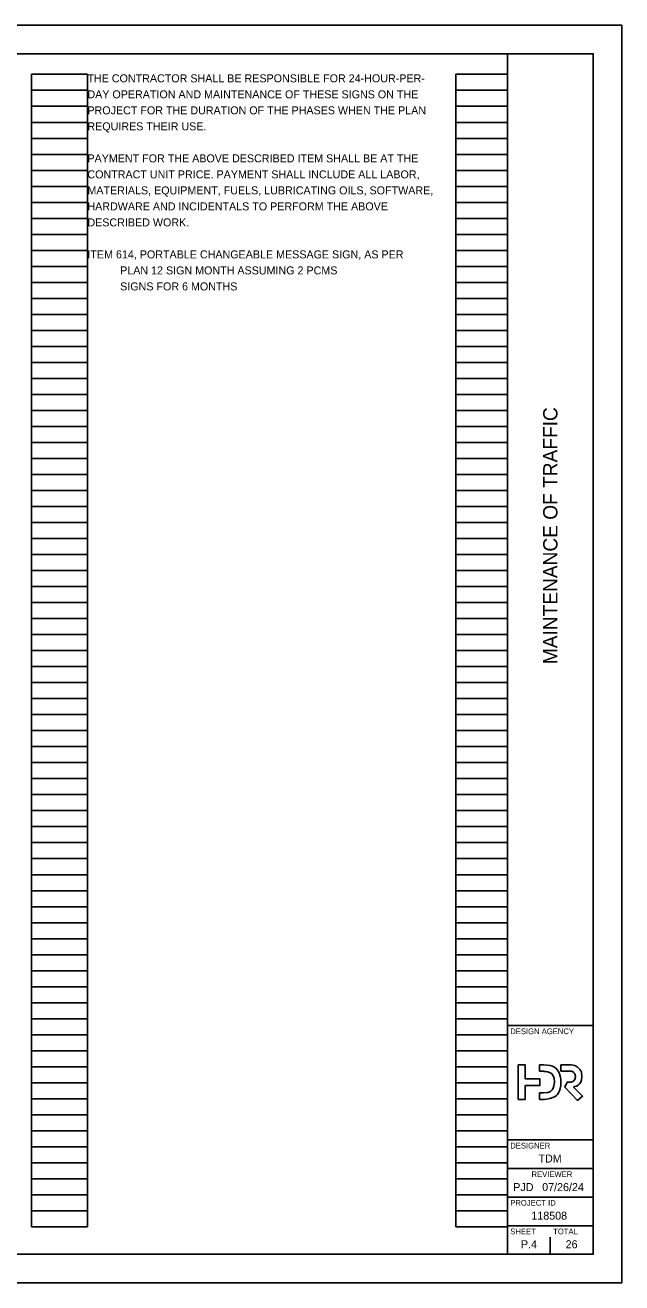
# Model space of a CAD drawing. Extents: x -9 to 65.1, y -15.6 to 23.2.
# Drawn here: x 23.57 to 34, y 0 to 22 of the extents above; entities that cross this region are included whole.
import ezdxf

# ---------------------------------------------------------------- set-up
doc = ezdxf.new("R2010")
doc.units = 0
for name, color, linetype in [('SH_Border', 7, 'Continuous'), ('SH_Cut_Line', 7, 'Continuous'), ('SH_Data', 7, 'Continuous'), ('SH_Text', 7, 'Continuous')]:
    doc.layers.add(name, color=color, linetype=linetype)

msp = doc.modelspace()

# ---------------------------------------------------------------- linework, layer by layer
at = {"layer": 'SH_Border'}
for p, q in [((32, 0.5), (32, 21.5)), ((32, 4.5), (33.5, 4.5)), ((32, 2.5), (33.5, 2.5)), ((32, 2), (33.5, 2)), ((32, 1.5), (33.5, 1.5)), ((32, 1), (33.5, 1))]:
    msp.add_line(p, q, dxfattribs=at)
msp.add_lwpolyline([(1.5, 21.5), (33.5, 21.5), (33.5, 0.5), (1.5, 0.5)], close=True, dxfattribs=at)
at = {"layer": 'SH_Cut_Line'}
msp.add_lwpolyline([(0, 0), (34, 0), (34, 22), (0, 22)], close=True, dxfattribs=at)
at = {"layer": 'SH_Data'}
for p, q in [((23.68, 0.98), (23.68, 21.14)), ((23.68, 21.14), (24.66, 21.14)), ((24.66, 0.98), (24.66, 21.14)), ((31.1, 0.98), (31.1, 21.14)), ((31.1, 21.14), (32, 21.14)), ((32, 0.98), (32, 21.14)), ((23.68, 20.86), (24.66, 20.86)), ((31.1, 20.86), (32, 20.86)), ((23.68, 20.58), (24.66, 20.58)), ((31.1, 20.58), (32, 20.58)), ((23.68, 20.3), (24.66, 20.3)), ((31.1, 20.3), (32, 20.3)), ((23.68, 20.02), (24.66, 20.02)), ((31.1, 20.02), (32, 20.02)), ((23.68, 19.74), (24.66, 19.74)), ((31.1, 19.74), (32, 19.74)), ((23.68, 19.46), (24.66, 19.46)), ((31.1, 19.46), (32, 19.46)), ((23.68, 19.18), (24.66, 19.18)), ((31.1, 19.18), (32, 19.18)), ((23.68, 18.9), (24.66, 18.9)), ((31.1, 18.9), (32, 18.9)), ((23.68, 18.62), (24.66, 18.62)), ((31.1, 18.62), (32, 18.62)), ((23.68, 18.34), (24.66, 18.34)), ((31.1, 18.34), (32, 18.34)), ((23.68, 18.06), (24.66, 18.06)), ((31.1, 18.06), (32, 18.06)), ((23.68, 17.78), (24.66, 17.78)), ((31.1, 17.78), (32, 17.78)), ((23.68, 17.5), (24.66, 17.5)), ((31.1, 17.5), (32, 17.5)), ((23.68, 17.22), (24.66, 17.22)), ((31.1, 17.22), (32, 17.22)), ((23.68, 16.94), (24.66, 16.94)), ((31.1, 16.94), (32, 16.94)), ((23.68, 16.66), (24.66, 16.66)), ((31.1, 16.66), (32, 16.66)), ((23.68, 16.38), (24.66, 16.38)), ((31.1, 16.38), (32, 16.38)), ((23.68, 16.1), (24.66, 16.1)), ((31.1, 16.1), (32, 16.1)), ((23.68, 15.82), (24.66, 15.82)), ((31.1, 15.82), (32, 15.82)), ((23.68, 15.54), (24.66, 15.54)), ((31.1, 15.54), (32, 15.54)), ((23.68, 15.26), (24.66, 15.26)), ((31.1, 15.26), (32, 15.26)), ((23.68, 14.98), (24.66, 14.98)), ((31.1, 14.98), (32, 14.98)), ((23.68, 14.7), (24.66, 14.7)), ((31.1, 14.7), (32, 14.7)), ((23.68, 14.42), (24.66, 14.42)), ((31.1, 14.42), (32, 14.42)), ((23.68, 14.14), (24.66, 14.14)), ((31.1, 14.14), (32, 14.14)), ((23.68, 13.86), (24.66, 13.86)), ((31.1, 13.86), (32, 13.86)), ((23.68, 13.58), (24.66, 13.58)), ((31.1, 13.58), (32, 13.58)), ((23.68, 13.3), (24.66, 13.3)), ((31.1, 13.3), (32, 13.3)), ((23.68, 13.02), (24.66, 13.02)), ((31.1, 13.02), (32, 13.02)), ((23.68, 12.74), (24.66, 12.74)), ((31.1, 12.74), (32, 12.74)), ((23.68, 12.46), (24.66, 12.46)), ((31.1, 12.46), (32, 12.46)), ((23.68, 12.18), (24.66, 12.18)), ((31.1, 12.18), (32, 12.18)), ((23.68, 11.9), (24.66, 11.9)), ((31.1, 11.9), (32, 11.9)), ((23.68, 11.62), (24.66, 11.62)), ((31.1, 11.62), (32, 11.62)), ((23.68, 11.34), (24.66, 11.34)), ((31.1, 11.34), (32, 11.34)), ((23.68, 11.06), (24.66, 11.06)), ((31.1, 11.06), (32, 11.06)), ((23.68, 10.78), (24.66, 10.78)), ((31.1, 10.78), (32, 10.78)), ((23.68, 10.5), (24.66, 10.5)), ((31.1, 10.5), (32, 10.5)), ((23.68, 10.22), (24.66, 10.22)), ((31.1, 10.22), (32, 10.22)), ((23.68, 9.94), (24.66, 9.94)), ((31.1, 9.94), (32, 9.94)), ((23.68, 9.66), (24.66, 9.66)), ((31.1, 9.66), (32, 9.66)), ((23.68, 9.38), (24.66, 9.38)), ((31.1, 9.38), (32, 9.38)), ((23.68, 9.1), (24.66, 9.1)), ((31.1, 9.1), (32, 9.1)), ((23.68, 8.82), (24.66, 8.82)), ((31.1, 8.82), (32, 8.82)), ((23.68, 8.54), (24.66, 8.54)), ((31.1, 8.54), (32, 8.54)), ((23.68, 8.26), (24.66, 8.26)), ((31.1, 8.26), (32, 8.26)), ((23.68, 7.98), (24.66, 7.98)), ((31.1, 7.98), (32, 7.98)), ((23.68, 7.7), (24.66, 7.7)), ((31.1, 7.7), (32, 7.7)), ((23.68, 7.42), (24.66, 7.42)), ((31.1, 7.42), (32, 7.42)), ((23.68, 7.14), (24.66, 7.14)), ((31.1, 7.14), (32, 7.14)), ((23.68, 6.86), (24.66, 6.86)), ((31.1, 6.86), (32, 6.86)), ((23.68, 6.58), (24.66, 6.58)), ((31.1, 6.58), (32, 6.58)), ((23.68, 6.3), (24.66, 6.3)), ((31.1, 6.3), (32, 6.3)), ((23.68, 6.02), (24.66, 6.02)), ((31.1, 6.02), (32, 6.02)), ((23.68, 5.74), (24.66, 5.74)), ((31.1, 5.74), (32, 5.74)), ((23.68, 5.46), (24.66, 5.46)), ((31.1, 5.46), (32, 5.46)), ((23.68, 5.18), (24.66, 5.18)), ((31.1, 5.18), (32, 5.18)), ((23.68, 4.9), (24.66, 4.9)), ((31.1, 4.9), (32, 4.9)), ((23.68, 4.62), (24.66, 4.62)), ((31.1, 4.62), (32, 4.62)), ((23.68, 4.34), (24.66, 4.34)), ((31.1, 4.34), (32, 4.34)), ((23.68, 4.06), (24.66, 4.06)), ((31.1, 4.06), (32, 4.06)), ((23.68, 3.78), (24.66, 3.78)), ((31.1, 3.78), (32, 3.78)), ((23.68, 3.5), (24.66, 3.5)), ((31.1, 3.5), (32, 3.5)), ((32.75, 3.5), (32.75, 3.5)), ((23.68, 3.22), (24.66, 3.22)), ((31.1, 3.22), (32, 3.22)), ((23.68, 2.94), (24.66, 2.94)), ((31.1, 2.94), (32, 2.94)), ((23.68, 2.66), (24.66, 2.66)), ((31.1, 2.66), (32, 2.66)), ((23.68, 2.38), (24.66, 2.38)), ((31.1, 2.38), (32, 2.38)), ((23.68, 2.1), (24.66, 2.1)), ((31.1, 2.1), (32, 2.1)), ((23.68, 1.82), (24.66, 1.82)), ((31.1, 1.82), (32, 1.82)), ((23.68, 1.54), (24.66, 1.54)), ((31.1, 1.54), (32, 1.54)), ((23.68, 1.26), (24.66, 1.26)), ((31.1, 1.26), (32, 1.26)), ((23.68, 0.98), (24.66, 0.98)), ((31.1, 0.98), (32, 0.98)), ((32.375, 0.675), (32.375, 0.675)), ((32.75, 0.5), (32.75, 0.8))]:
    msp.add_line(p, q, dxfattribs=at)
msp.add_lwpolyline([(32.565, 3.571), (32.311, 3.571), (32.311, 3.813), (32.189, 3.813), (32.189, 3.209), (32.311, 3.209), (32.311, 3.451), (32.565, 3.451)], close=True, dxfattribs=at)
for points in [[(32.634, 3.813), (32.562, 3.813), (32.562, 3.7), (32.634, 3.7)], [(33.063, 3.813), (32.935, 3.813), (32.935, 3.704), (33.072, 3.704)], [(32.634, 3.322), (32.562, 3.322), (32.562, 3.209), (32.634, 3.209)], [(32.936, 3.511), (32.936, 3.511), (32.936, 3.511), (32.936, 3.512), (32.936, 3.512)], [(33.077, 3.51), (33.043, 3.51), (33.003, 3.424), (33.226, 3.192), (33.313, 3.265), (33.155, 3.425)]]:
    msp.add_lwpolyline(points, dxfattribs=at)
for points in [[(32.936, 3.512), (32.936, 3.512), (32.935, 3.686), (32.808, 3.813), (32.634, 3.813)], [(33.239, 3.759), (33.239, 3.759), (33.193, 3.802), (33.141, 3.813), (33.063, 3.813)], [(33.302, 3.605), (33.302, 3.605), (33.302, 3.668), (33.284, 3.716), (33.239, 3.759)], [(32.634, 3.7), (32.634, 3.7), (32.744, 3.7), (32.822, 3.622), (32.822, 3.511)], [(33.072, 3.704), (33.072, 3.704), (33.113, 3.704), (33.141, 3.696), (33.161, 3.676)], [(33.189, 3.607), (33.189, 3.607), (33.189, 3.546), (33.136, 3.51), (33.077, 3.51)], [(33.155, 3.425), (33.155, 3.425), (33.242, 3.441), (33.302, 3.521), (33.302, 3.605)], [(33.161, 3.676), (33.161, 3.676), (33.179, 3.658), (33.189, 3.634), (33.189, 3.607)], [(32.822, 3.511), (32.822, 3.511), (32.822, 3.4), (32.744, 3.322), (32.634, 3.322)], [(32.634, 3.209), (32.634, 3.209), (32.808, 3.209), (32.935, 3.336), (32.936, 3.511)]]:
    msp.add_open_spline(points, degree=3, dxfattribs=at)

# ---------------------------------------------------------------- texts
msp.add_text('MAINTENANCE OF TRAFFIC', height=0.25, rotation=90, dxfattribs=at).set_placement((32.875, 10.822))
for s, height, p in [('DESIGN AGENCY', 0.1, (32.05, 4.35)), ('DESIGNER', 0.1, (32.05, 2.35)), ('TDM', 0.14, (32.543, 2.105)), ('REVIEWER', 0.1, (32.422, 1.85)), ('PJD', 0.14, (32.103, 1.605)), ('07/26/24', 0.14, (32.608, 1.605)), ('PROJECT ID', 0.1, (32.05, 1.35)), ('118508', 0.14, (32.419, 1.105)), ('SHEET', 0.1, (32.05, 0.85)), ('TOTAL', 0.1, (32.8, 0.85)), ('P.4', 0.14, (32.237, 0.605)), ('26', 0.14, (33.018, 0.605))]:
    msp.add_text(s, height=height, dxfattribs=at).set_placement(p)
at = {"layer": 'SH_Text'}
for s, p in [('THE CONTRACTOR SHALL BE RESPONSIBLE FOR 24-HOUR-PER-', (24.66, 21)), ('DAY OPERATION AND MAINTENANCE OF THESE SIGNS ON THE', (24.66, 20.72)), ('PROJECT FOR THE DURATION OF THE PHASES WHEN THE PLAN', (24.66, 20.44)), ('REQUIRES THEIR USE.', (24.66, 20.16)), ('PAYMENT FOR THE ABOVE DESCRIBED ITEM SHALL BE AT THE', (24.66, 19.6)), ('CONTRACT UNIT PRICE. PAYMENT SHALL INCLUDE ALL LABOR,', (24.66, 19.32)), ('MATERIALS, EQUIPMENT, FUELS, LUBRICATING OILS, SOFTWARE,', (24.66, 19.04)), ('HARDWARE AND INCIDENTALS TO PERFORM THE ABOVE', (24.66, 18.76)), ('DESCRIBED WORK.', (24.66, 18.48)), ('ITEM 614, PORTABLE CHANGEABLE MESSAGE SIGN, AS PER', (24.66, 17.92)), ('           PLAN 12 SIGN MONTH ASSUMING 2 PCMS', (24.66, 17.64)), ('           SIGNS FOR 6 MONTHS', (24.66, 17.36))]:
    msp.add_text(s, height=0.14, dxfattribs=at).set_placement(p)

doc.saveas('drawing.dxf')
